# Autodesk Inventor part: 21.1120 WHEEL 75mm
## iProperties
Created: 2007-03
Part Number: 21.1120 WHEEL 75mm
Material: Rubber
Document SubType Name: Modeling
Designer: Andy Moles
Density: 0.93 g/cm^3
Author: Andy Moles
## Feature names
1. Extrusion1
2. Fillet1
3. Extrusion2
4. Mirror1
